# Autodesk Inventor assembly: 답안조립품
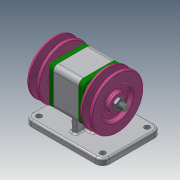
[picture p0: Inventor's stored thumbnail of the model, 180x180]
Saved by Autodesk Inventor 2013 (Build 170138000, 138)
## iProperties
Created: 2020-11
Part Number: 답안조립품
Document SubType Name: Assembly
Designer: 00
Author: 00
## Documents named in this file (10)
- C:\Users\00\Desktop\701106V1013\답안조립품.iam
- C:\Users\00\Desktop\701106V1013\본체.ipt
- C:\Users\00\Desktop\701106V1013\V-벨트풀리.ipt
- C:\Users\00\Desktop\701106V1013\너트 M10x1.ipt
- C:\Users\00\Desktop\701106V1013\베어링 6004.ipt
- C:\Users\00\Desktop\701106V1013\볼트 M4.ipt
- C:\Users\00\Desktop\701106V1013\오일 실 17 30 5.ipt
- C:\Users\00\Desktop\701106V1013\축.ipt
- C:\Users\00\Desktop\701106V1013\커버.ipt
- C:\Users\00\Desktop\701106V1013\키 5 x 5 x 12.ipt
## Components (2 placed, 1 different names)
1. V-벨트풀리:1
2. V-벨트풀리:2
## Component patterns: 구성요소 패턴 1:2 (2 elements), 구성요소 패턴 3:2 (2 elements)
